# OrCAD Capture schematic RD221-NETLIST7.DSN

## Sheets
1 3: size A3
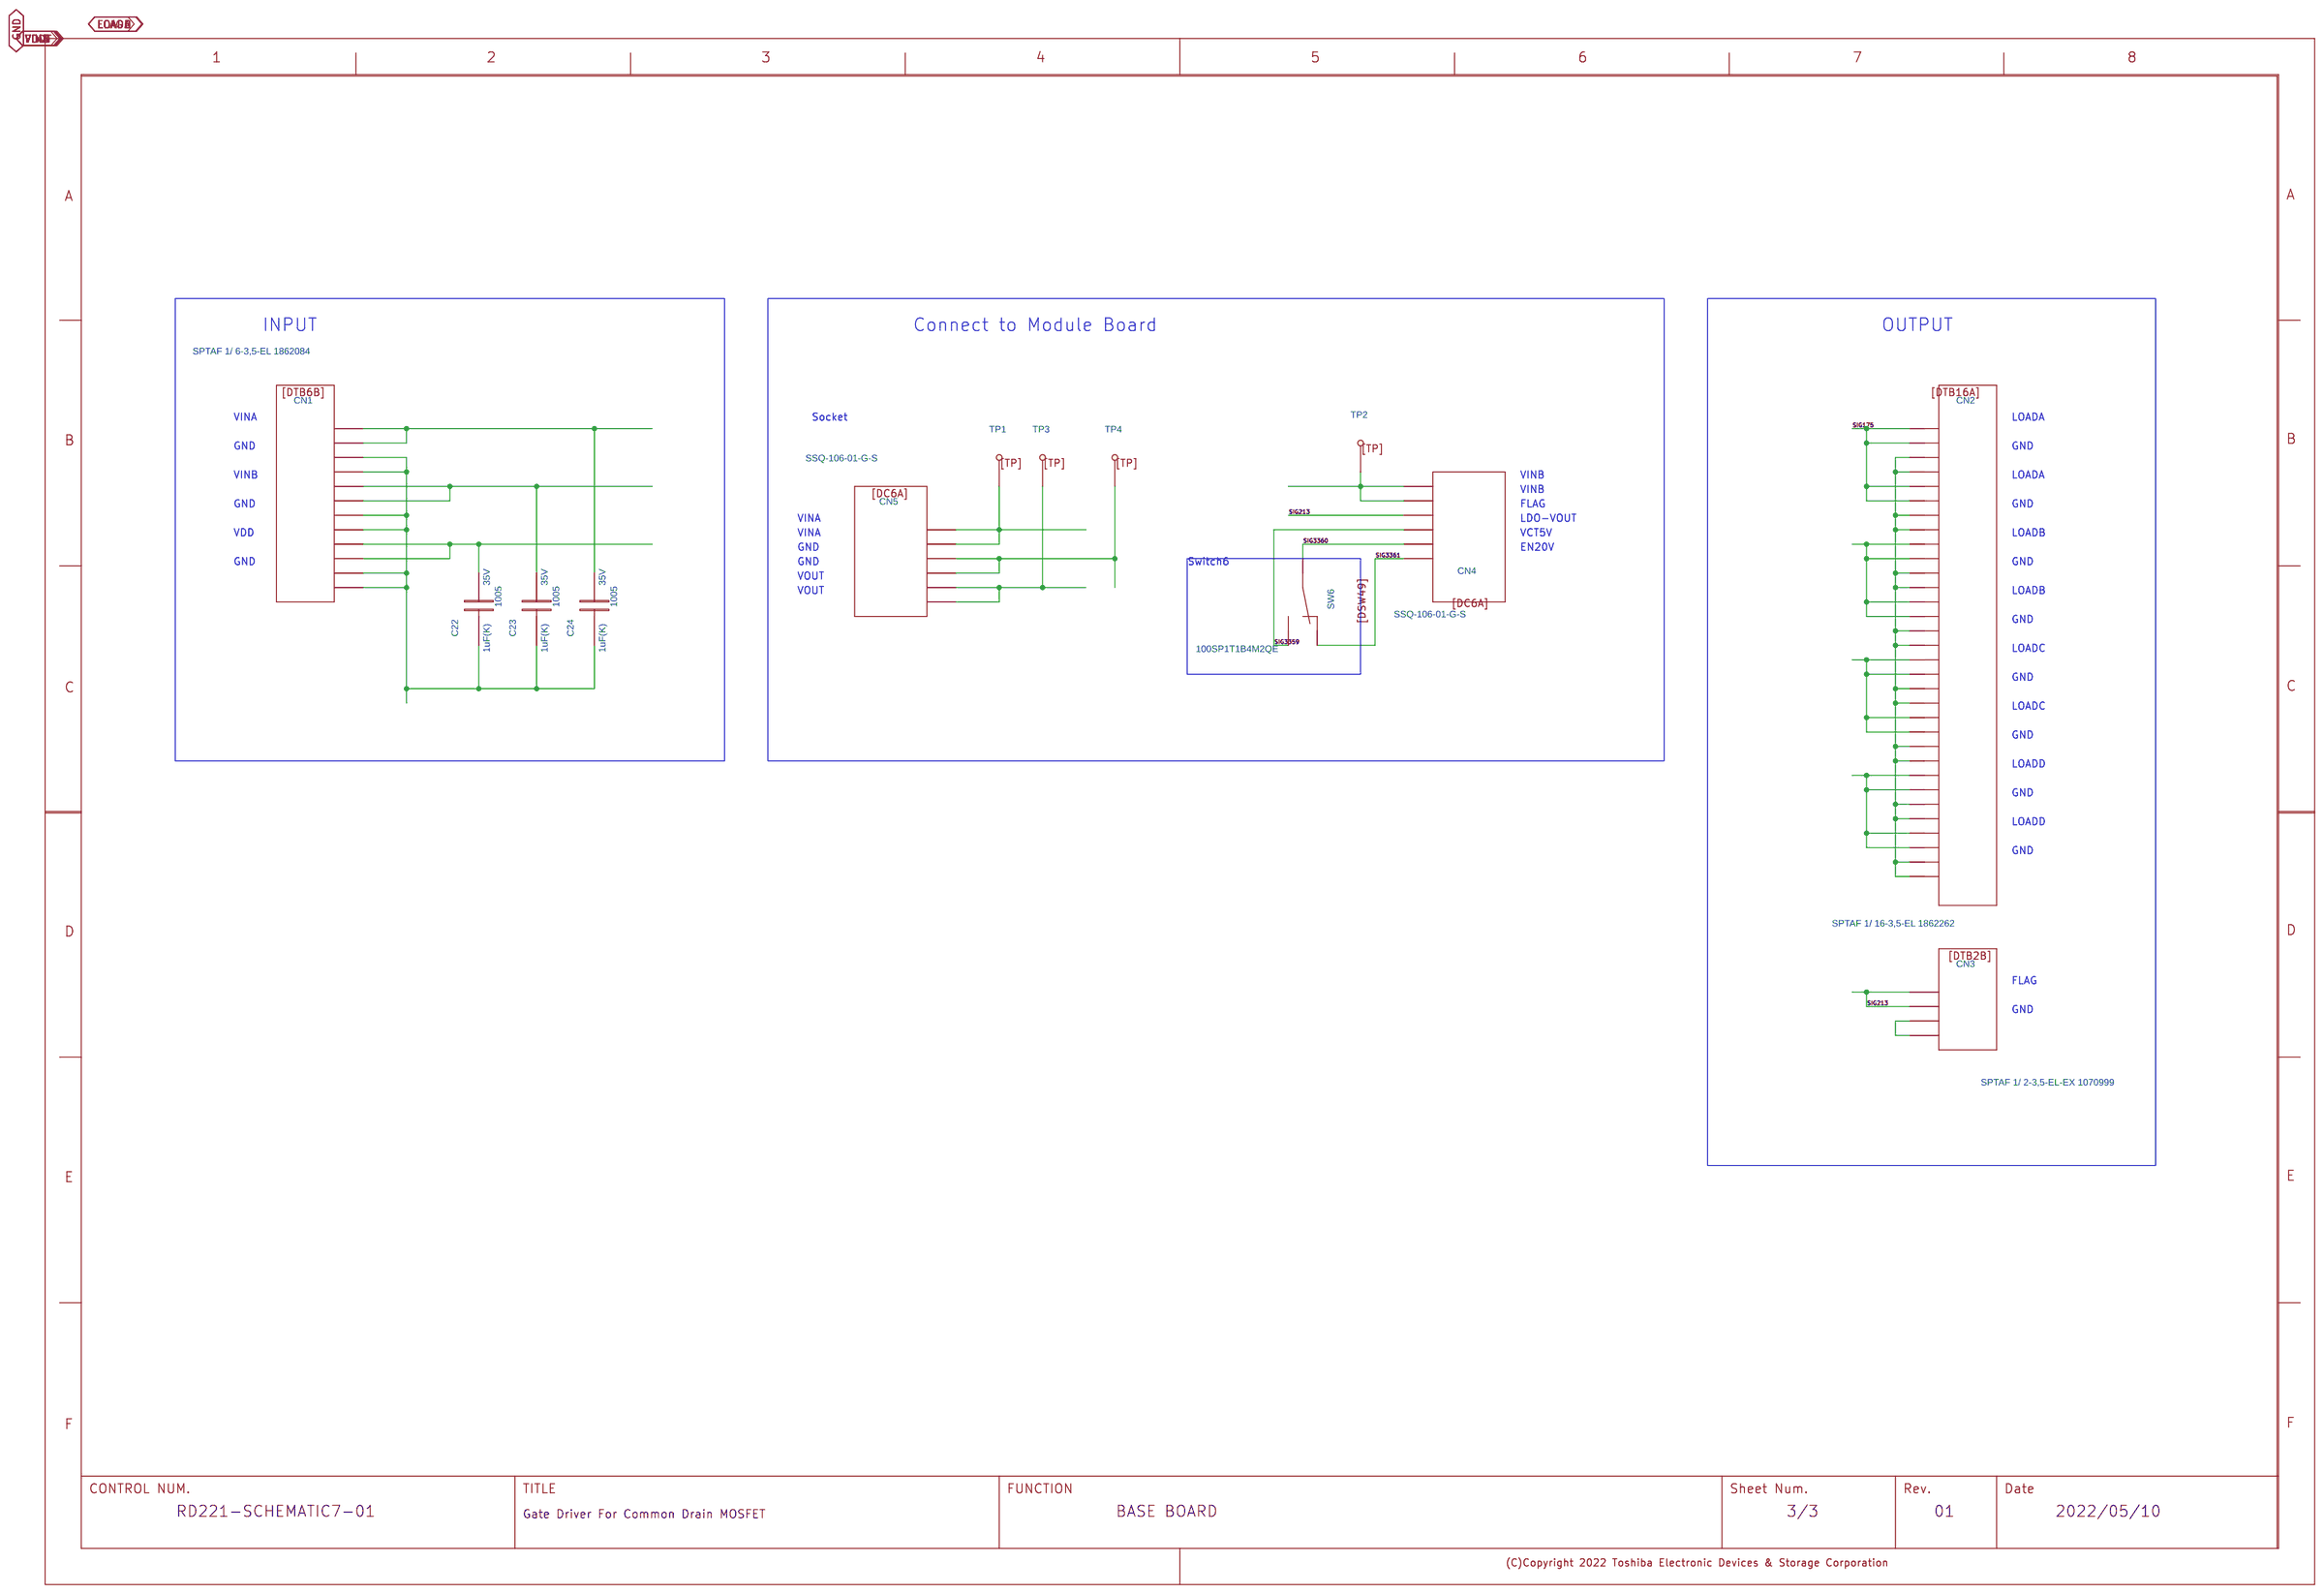
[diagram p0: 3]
2 2: size A3
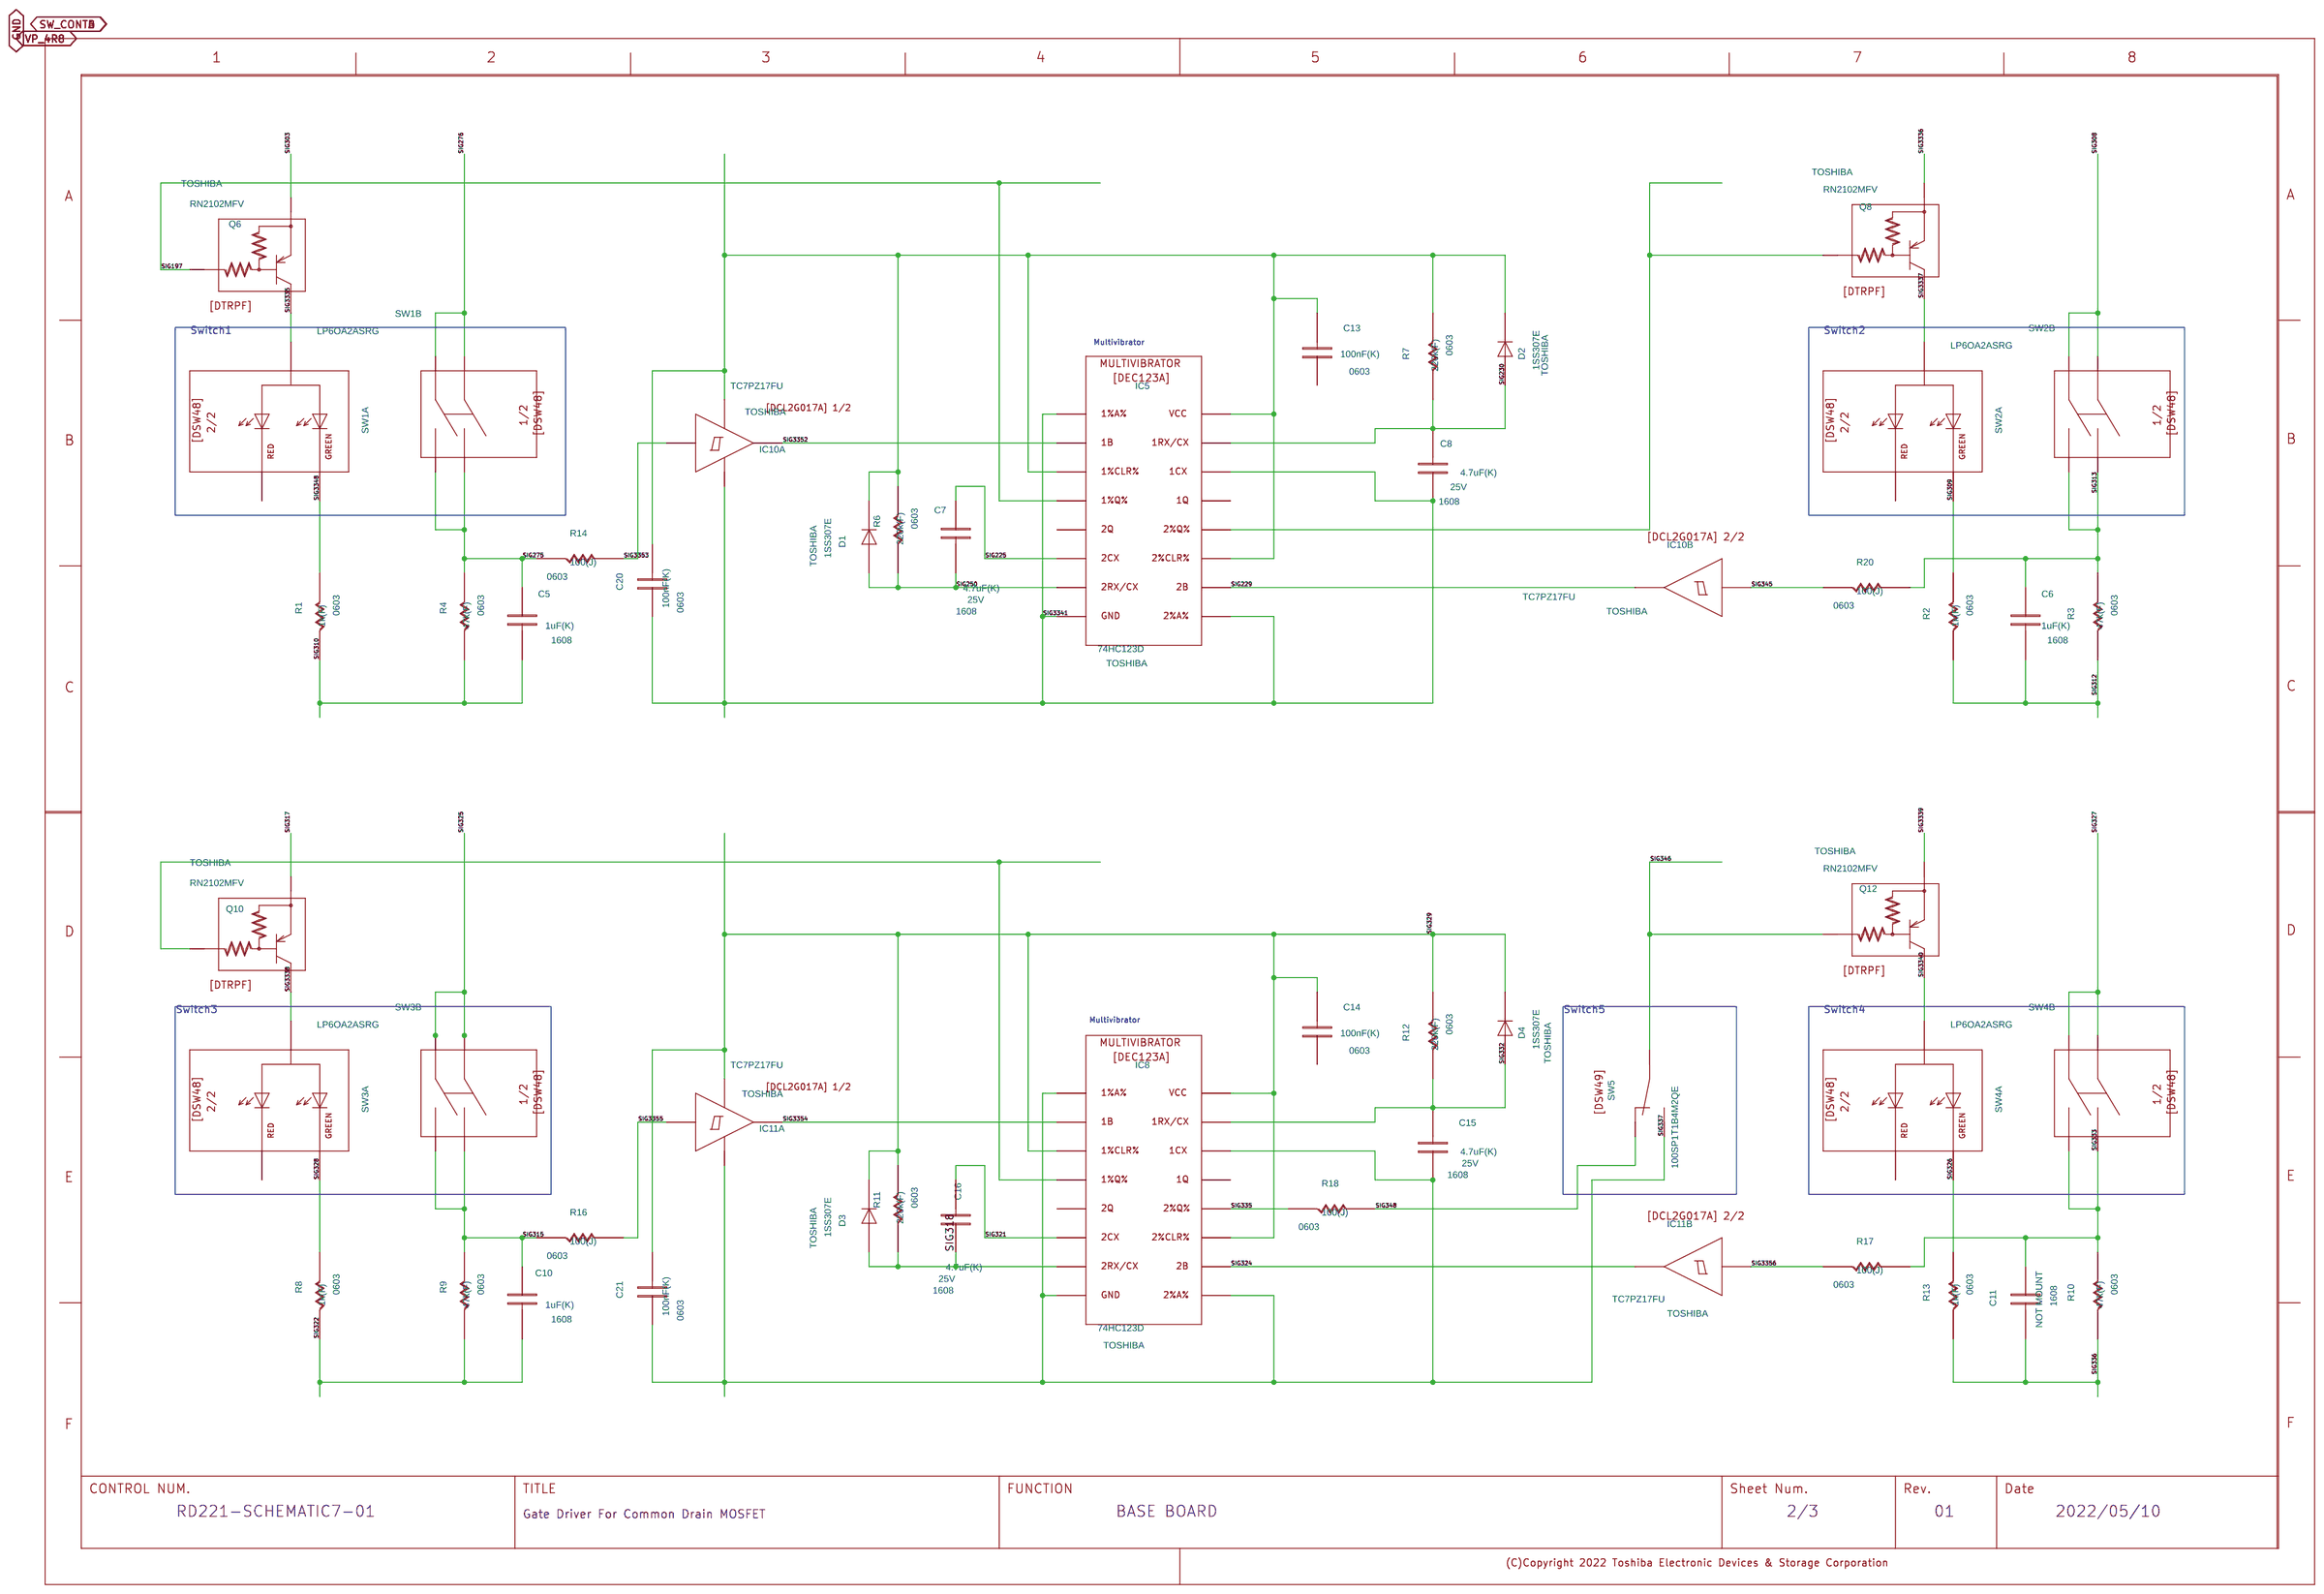
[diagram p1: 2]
3 1: size A3
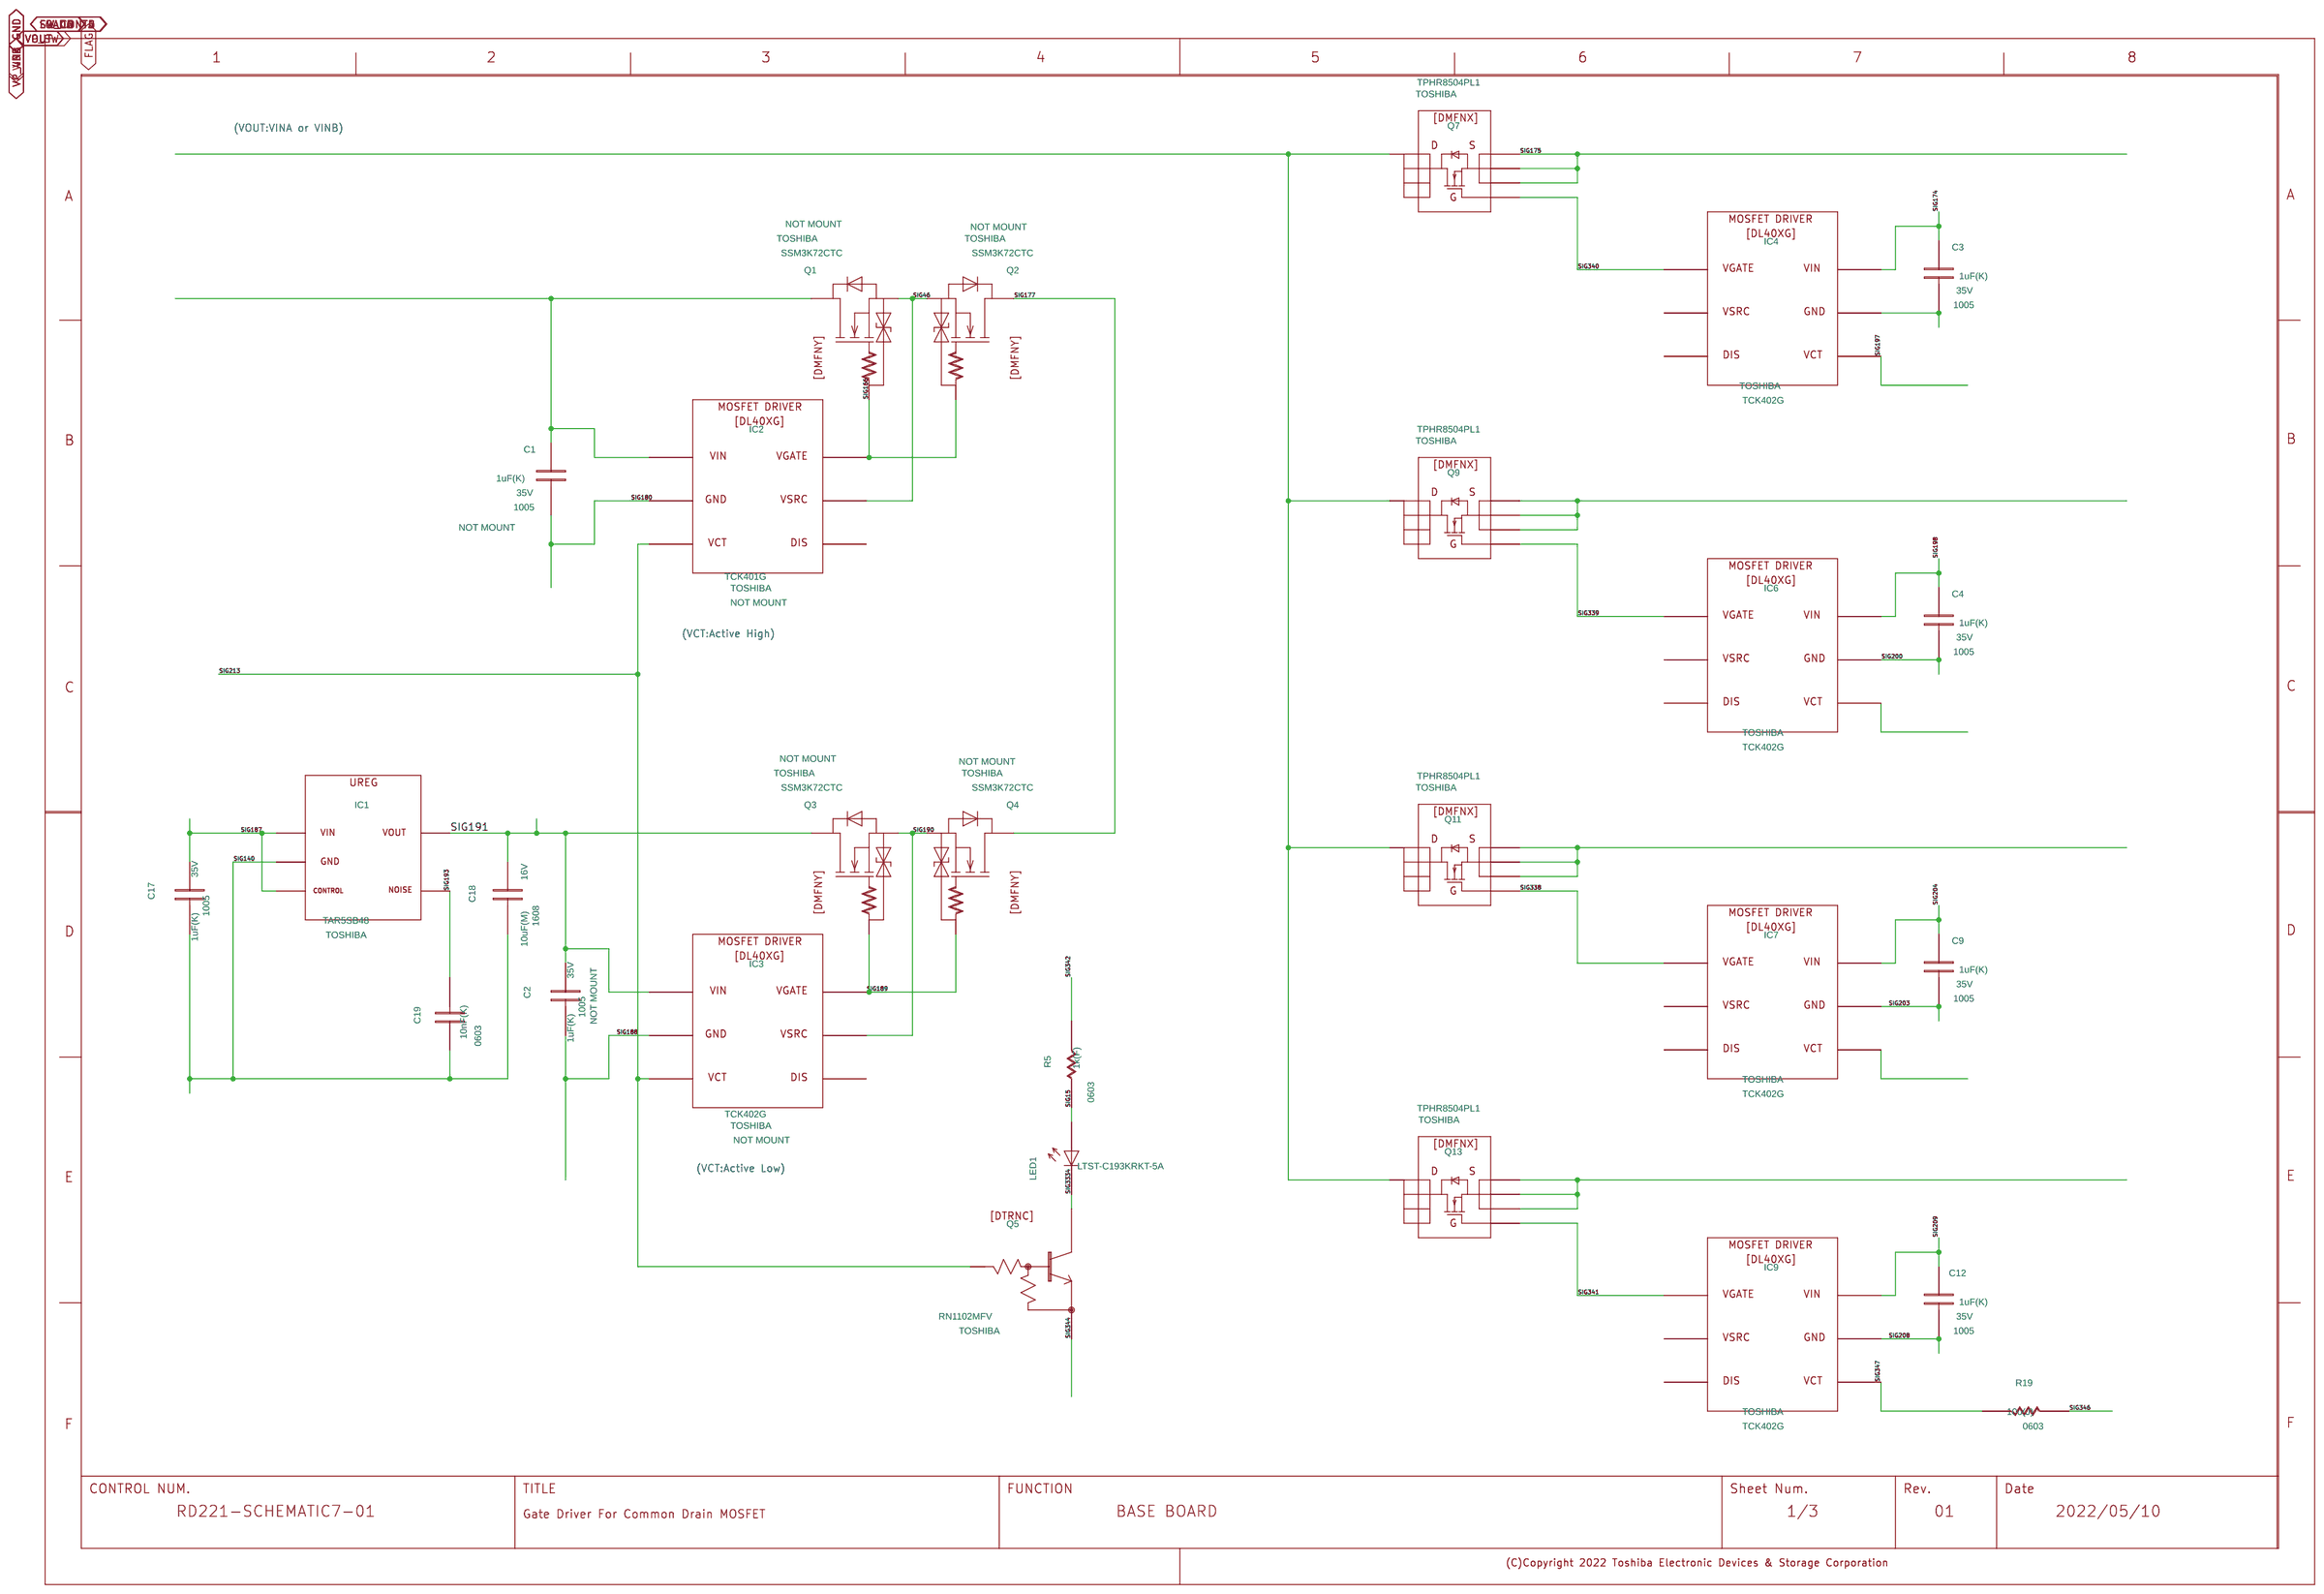
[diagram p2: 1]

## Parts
sheet 1
C1  DC
C2  DC
C3  DC
C4  DC
C9  DC
C12  DC
C17  DC
C18  DC
C19  DC
IC1  DL5SBXX
IC2  DL40XG
IC3  DL40XG
IC4  DL40XG
IC6  DL40XG
IC7  DL40XG
IC9  DL40XG
LED1  DLED
Q1  DMFNY
Q2  DMFNY
Q3  DMFNY
Q4  DMFNY
Q5  DTRNC
Q7  DMFNX
Q9  DMFNX
Q11  DMFNX
Q13  DMFNX
R5  DR
R19  DR
U?#2  WAKU_DEF100
sheet 2
C5  DC
C6  DC
C7  DC
C8  DC
C10  DC
C11  DC
C13  DC
C14  DC
C15  DC
C16  DC
C20  DC
C21  DC
D1  DD
D2  DD
D3  DD
D4  DD
IC5  DEC123A
IC8  DEC123A
IC10  DCL2G017A_1  (sections A,B)
IC11  DCL2G017A_1  (sections A,B)
Q6  DTRPF
Q8  DTRPF
Q10  DTRPF
Q12  DTRPF
R1  DR
R2  DR
R3  DR
R4  DR
R6  DR
R7  DR
R8  DR
R9  DR
R10  DR
R11  DR
R12  DR
R13  DR
R14  DR
R16  DR
R17  DR
R18  DR
R20  DR
SW1  DSW48_1  (sections A,B)
SW2  DSW48_1  (sections A,B)
SW3  DSW48_1  (sections A,B)
SW4  DSW48_1  (sections A,B)
SW5  DSW49
U?#1  WAKU_DEF100
sheet 3
C22  DC
C23  DC
C24  DC
CN1  DTB6B
CN2  DTB16A
CN3  DTB2B
CN4  DC6A
CN5  DC6A
SW6  DSW49
TP1  DTP
TP2  DTP
TP3  DTP
TP4  DTP
U?#3  WAKU_DEF100

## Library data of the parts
C1 C2 = DC: COMP: DP0000016125; COMPONENTNAME: DP0000016125_package; FUNCN: DP0000016125; GCOUNT: 1; MAXGCOUNT: 1; NOTMOUNT: NOT MOUNT; OUMEPARTTYPE: C; SIZECODESMD: 1005; VAL1: 1uF(K); VAL2: 35V; VAL3: GRM155R6YA105KE11D
C3 C4 C9 C12 C17 C22-C24 = DC: COMP: DP0000016125; COMPONENTNAME: DP0000016125_package; FUNCN: DP0000016125; GCOUNT: 1; MAXGCOUNT: 1; OUMEPARTTYPE: C; SIZECODESMD: 1005; VAL1: 1uF(K); VAL2: 35V; VAL3: GRM155R6YA105KE11D
C18 = DC: COMP: DP0008993000; COMPONENTNAME: DP0008993000_package; FUNCN: DP0008993000; GCOUNT: 1; MAXGCOUNT: 1; OUMEPARTTYPE: C; SIZECODESMD: 1608; VAL1: 10uF(M); VAL2: 16V; VAL3: GRM188R61C106MA73D
C19 = DC: COMP: DP0000015127; COMPONENTNAME: DP0000015127; FUNCN: DP0000015127; GCOUNT: 1; MAXGCOUNT: 1; OUMEPARTTYPE: C; SIZECODESMD: 0603; VAL1: 10nF(K); VAL2: 16V; VAL3: GRM033B31C103KA12D
IC1 = DL5SBXX: COMP: DP0010569000; COMPONENTNAME: DP0010569000_package; FUNCN: DP0010569000; GCOUNT: 1; MAXGCOUNT: 1; OUMEPARTTYPE: IC; SAVEAREA0: -49052,-25553,79781,45765; SAVECOUNT: 22; UPDATEDATE: 2021/11/04; UPDATETIME: 15:26:52; USERCOMPTEXT3: TOSHIBA; VAL1: TAR5SB48; VAL3: TAR5SB48
IC2 = DL40XG: COMP: DP0010565000; COMPONENTNAME: DP0010565000_package; FUNCN: DP0010565000; GCOUNT: 1; MAXGCOUNT: 1; NOTMOUNT: NOT MOUNT; OUMEPARTTYPE: IC; SAVEAREA0: -25087,-13639,60802,33906; UPDATEDATE: 2021/11/04; UPDATETIME: 14:00:32; UPDATEUSER: t5459927; USERCOMPTEXT3: TOSHIBA; VAL1: TCK401G; VAL3: TCK401G
IC3 = DL40XG: COMP: DP0010566000; COMPONENTNAME: DP0010566000_package; FUNCN: DP0010566000; GCOUNT: 1; MAXGCOUNT: 1; NOTMOUNT: NOT MOUNT; OUMEPARTTYPE: IC; SAVEAREA0: -25087,-13639,60802,33906; UPDATEDATE: 2021/11/04; UPDATETIME: 14:00:32; UPDATEUSER: t5459927; USERCOMPTEXT3: TOSHIBA; VAL1: TCK402G; VAL3: TCK402G
IC4 IC6 IC7 IC9 = DL40XG: COMP: DP0010566000; COMPONENTNAME: DP0010566000_package; FUNCN: DP0010566000; GCOUNT: 1; MAXGCOUNT: 1; OUMEPARTTYPE: IC; SAVEAREA0: -25087,-13639,60802,33906; UPDATEDATE: 2021/11/04; UPDATETIME: 14:00:32; UPDATEUSER: t5459927; USERCOMPTEXT3: TOSHIBA; VAL1: TCK402G; VAL3: TCK402G
LED1 = DLED: COMP: DP0010573000; COMPONENTNAME: DP0010573000_package; FUNCN: DP0010573000; GCOUNT: 1; MAXGCOUNT: 1; OUMEPARTTYPE: DS; VAL3: LTST-C193KRKT-5A
Q1-Q4 = DMFNY: COMP: DP0010564000; COMPONENTNAME: DP0010564000_package; FUNCN: DP0010564000; GCOUNT: 1; MAXGCOUNT: 1; NOTMOUNT: NOT MOUNT; OUMEPARTTYPE: Q; USERCOMPTEXT3: TOSHIBA; VAL1: SSM3K72CTC; VAL3: SSM3K72CTC
Q5 = DTRNC: COMP: DP0010015000; COMPONENTNAME: DP0010015000_package; FUNCN: DP0010015000; GCOUNT: 1; MAXGCOUNT: 1; OUMEPARTTYPE: Q; USERCOMPTEXT1: RN1102MFV; USERCOMPTEXT3: TOSHIBA; VAL1: RN1114MFV; VAL3: RN1114MFV
Q7 Q9 Q11 Q13 = DMFNX: COMP: DP0010567000; COMPONENTNAME: DP0010567000_package; FUNCN: DP0010567000; GCOUNT: 1; MAXGCOUNT: 1; OUMEPARTTYPE: Q; USERCOMPTEXT3: TOSHIBA; VAL1: TPHR8504PL1; VAL3: TPHR8504PL1
R1 R2 R5 R8 R13 = DR: COMP: DP0000152048; COMPONENTNAME: DP0000152048; FUNCN: DP0000152048; GCOUNT: 1; MAXGCOUNT: 1; OUMEPARTTYPE: R; SIZECODESMD: 0603; VAL1: 1k(F); VAL2: 50mW; VAL3: ERJ1GNF1001C
R14 R16-R20 = DR: COMP: DP0000155000; COMPONENTNAME: DP0000155000_package; FUNCN: DP0000155000; GCOUNT: 1; MAXGCOUNT: 1; OUMEPARTTYPE: R; SIZECODESMD: 0603; VAL1: 100(J); VAL2: 50mW; VAL3: RK73B1HTTC101J
U?#2 = WAKU_DEF100: DATE: 2022/05/10; DRAWINGNUMBER: RD221-SCHEMATIC7-01; FUNCTION: BASE BOARD; REVISION: 01; SAVEAREA0: 148187,-66180,486823,89919; SAVECOUNT: 6; SHEETNUMBER: 1/3; TITLE: Gate Driver For Common Drain MOSFET; UPDATEDATE: 2022/05/17; UPDATETIME: 07:15:59
C5 C6 C10 = DC: COMP: DP0000149011; COMPONENTNAME: DP0000149011_package; FUNCN: DP0000149011; GCOUNT: 1; MAXGCOUNT: 1; OUMEPARTTYPE: C; SIZECODESMD: 1608; VAL1: 1uF(K); VAL2: 35V; VAL3: GMK107BJ105KA-T
C7 C8 C15 C16 = DC: COMP: DP0000017116; COMPONENTNAME: DP0000017116_package; FUNCN: DP0000017116; GCOUNT: 1; MAXGCOUNT: 1; OUMEPARTTYPE: C; SIZECODESMD: 1608; VAL1: 4.7uF(K); VAL2: 25V; VAL3: GRM188R61E475KE15D
C11 = DC: COMP: DP0000149011; COMPONENTNAME: DP0000149011_package; FUNCN: DP0000149011; GCOUNT: 1; MAXGCOUNT: 1; NOTMOUNT: NOT MOUNT; OUMEPARTTYPE: C; SIZECODESMD: 1608; VAL1: 1uF(K); VAL2: 35V; VAL3: GMK107BJ105KA-T
C13 C14 C20 C21 = DC: COMP: DP0000015406; COMPONENTNAME: DP0000015406_package; FUNCN: DP0000015406; GCOUNT: 1; MAXGCOUNT: 1; OUMEPARTTYPE: C; SIZECODESMD: 0603; VAL1: 100nF(K); VAL2: 16V; VAL3: GRM033R61C104KE14D
D1-D4 = DD: COMP: DP0005002000; COMPONENTNAME: DP0005002000_package; FUNCN: DP0005002000; GCOUNT: 1; MAXGCOUNT: 1; OUMEPARTTYPE: D; USERCOMPTEXT3: TOSHIBA; VAL1: 1SS307E; VAL3: 1SS307E
IC5 IC8 = DEC123A: COMP: DP0010568000; COMPONENTNAME: DP0010568000_package; FUNCN: DP0010568000; GCOUNT: 1; MAXGCOUNT: 1; OUMEPARTTYPE: IC; USERCOMPTEXT3: TOSHIBA; VAL1: 74HC123D; VAL3: 74HC123D
IC10 IC11 = DCL2G017A_1: COMP: DP0010608000; COMPONENTNAME: DCL2G017A_pinAssign_DCL2G017A_1_function; CaptureCellPackProp: DCL2G017A_1A; FUNCN: DCL2G017A_1_function; GCOUNT: 1; MAXGCOUNT: 1; OUMEPARTTYPE: IC; USERCOMPTEXT3: TOSHIBA; VAL1: TC7PZ17FU; VAL3: TC7PZ17FU
Q6 Q8 Q10 Q12 = DTRPF: COMP: DP0010570000; COMPONENTNAME: DP0010570000_package; FUNCN: DP0010570000; GCOUNT: 1; MAXGCOUNT: 1; OUMEPARTTYPE: Q; USERCOMPTEXT3: TOSHIBA; VAL1: RN2102MFV; VAL3: RN2102MFV
R3 R4 R9 R10 = DR: COMP: DP0000152088; COMPONENTNAME: DP0000152088; FUNCN: DP0000152088; GCOUNT: 1; MAXGCOUNT: 1; OUMEPARTTYPE: R; SIZECODESMD: 0603; VAL1: 47k(F); VAL2: 50mW; VAL3: ERJ1GNF4702C
R6 R11 = DR: COMP: DP0000152104; COMPONENTNAME: DP0000152104; FUNCN: DP0000152104; GCOUNT: 1; MAXGCOUNT: 1; OUMEPARTTYPE: R; SIZECODESMD: 0603; VAL1: 220k(F); VAL2: 50mW; VAL3: ERJ1GNF2203C
R7 R12 = DR: COMP: DP0000155128; COMPONENTNAME: DP0000155128; FUNCN: DP0000155128; GCOUNT: 1; MAXGCOUNT: 1; OUMEPARTTYPE: R; SIZECODESMD: 0603; VAL1: 220k(F); VAL2: 50mW; VAL3: RK73B1HTTC224J
SW1 SW4 = DSW48_1: COMP: DP0010571000; COMPONENTNAME: DSW48_pinAssign_DSW48_1_function; CaptureCellPackProp: DSW48_1B; FUNCN: DSW48_1_function; GCOUNT: 1; MAXGCOUNT: 1; OUMEPARTTYPE: S; VAL3: LP6OA2ASRG; ADSCNVFLAG: ON; FNLEADFREETHET1GT2GMCTH1: N_N_N; MOUNTINGFORM: ‘}“üŽÀ‘•; NUMBEROFPOSITIO: 2POS; OUMECLASSIFICATION: vbV{^^^NgXCb`; OUMEMAKER: ZZZ bè; OUMEMAKERKATAMEI: LP6OA2ASRG; RATEDCURRENT: 12m; RATEDVOLTAGE: 12
SW2 = DSW48_1: COMP: DP0010571000; COMPONENTNAME: DSW48_pinAssign_DSW48_2_function; CaptureCellPackProp: DSW48_1A; FUNCN: DSW48_2_function; GCOUNT: 1; MAXGCOUNT: 1; OUMEPARTTYPE: S; VAL3: LP6OA2ASRG; ADSCNVFLAG: ON; FNLEADFREETHET1GT2GMCTH1: N_N_N; MOUNTINGFORM: ‘}“üŽÀ‘•; NUMBEROFPOSITIO: 2POS; OUMECLASSIFICATION: vbV{^^^NgXCb`; OUMEMAKER: ZZZ bè; OUMEMAKERKATAMEI: LP6OA2ASRG; RATEDCURRENT: 12m; RATEDVOLTAGE: 12
SW3 = DSW48_1: ADSCNVFLAG: ON; COMP: DP0010571000; COMPONENTNAME: DSW48_pinAssign_DSW48_2_function; CaptureCellPackProp: DSW48_1A; FNLEADFREETHET1GT2GMCTH1: N_N_N; FUNCN: DSW48_2_function; GCOUNT: 1; MAXGCOUNT: 1; MOUNTINGFORM: ‘}“üŽÀ‘•; NUMBEROFPOSITIO: 2POS; OUMECLASSIFICATION: vbV{^^^NgXCb`; OUMEMAKER: ZZZ bè; OUMEMAKERKATAMEI: LP6OA2ASRG; OUMEPARTTYPE: S; RATEDCURRENT: 12m; RATEDVOLTAGE: 12; VAL3: LP6OA2ASRG
SW5 SW6 = DSW49: COMP: DP0010575000; COMPONENTNAME: DP0010575000_package; FUNCN: DP0010575000; GCOUNT: 1; MAXGCOUNT: 1; OUMEPARTTYPE: S; VAL3: 100SP1T1B4M2QE
U?#1 = WAKU_DEF100: DATE: 2022/05/10; DRAWINGNUMBER: RD221-SCHEMATIC7-01; FUNCTION: BASE BOARD; REVISION: 01; SAVEAREA0: 148187,-66180,486823,89919; SAVECOUNT: 6; SHEETNUMBER: 2/3; TITLE: Gate Driver For Common Drain MOSFET; UPDATEDATE: 2022/05/16; UPDATETIME: 16:52:10
CN1 = DTB6B: COMP: DP0010576000; COMPONENTNAME: DP0010576000_package; FUNCN: DP0010576000; GCOUNT: 1; MAXGCOUNT: 1; OUMEPARTTYPE: TB; VAL3: SPTAF 1/ 6-3,5-EL 1862084
CN2 = DTB16A: COMP: DP0010577000; COMPONENTNAME: DP0010577000_package; FUNCN: DP0010577000; GCOUNT: 1; MAXGCOUNT: 1; OUMEPARTTYPE: TB; VAL3: SPTAF 1/ 16-3,5-EL 1862262
CN3 = DTB2B: COMP: DP0010578000; COMPONENTNAME: DP0010578000_package; FUNCN: DP0010578000; GCOUNT: 1; MAXGCOUNT: 1; OUMEPARTTYPE: TB; VAL3: SPTAF 1/ 2-3,5-EL-EX 1070999
CN4 CN5 = DC6A: COMP: DP0010574000; COMPONENTNAME: DP0010574000_package; FUNCN: DP0010574000; GCOUNT: 1; MAXGCOUNT: 1; OUMEPARTTYPE: CN; VAL3: SSQ-106-01-G-S
TP1-TP4 = DTP: COMP: DP9000817000; COMPONENTNAME: DP9000817000_package; FUNCN: DP9000817000; GCOUNT: 1; MAXGCOUNT: 1; NOTMOUNT: NOT MOUNT; OUMEPARTTYPE: TP
U?#3 = WAKU_DEF100: DATE: 2022/05/10; DRAWINGNUMBER: RD221-SCHEMATIC7-01; FUNCTION: BASE BOARD; REVISION: 01; SAVEAREA0: 148187,-66180,486823,89919; SAVECOUNT: 6; SHEETNUMBER: 3/3; TITLE: Gate Driver For Common Drain MOSFET; UPDATEDATE: 2022/05/10; UPDATETIME: 18:03:24

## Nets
GND: C1.2 C2.2 C3.2 C4.2 C5.2 C6.2 C8.1 C9.2 C10.2 C11.2 C12.2 C13.1 C14.1 C15.1 C17.2 C18.2 C19.1 C20.1 C21.1 C22.2 C23.2 C24.2 CN1.2 CN1.2A CN1.4 CN1.4A CN1.6 CN1.6A CN2.2 CN2.2A CN2.4 CN2.4A CN2.6 CN2.6A CN2.8 CN2.8A CN2.10 CN2.10A CN2.12 CN2.12A CN2.14 CN2.14A CN2.16 CN2.16A CN3.2 CN3.2A CN5.3 CN5.4 IC1.2 IC2.B2 IC3.B2 IC4.B2 IC5.1 IC5.8 IC5.9 IC5.14 IC6.B2 IC7.B2 IC8.1 IC8.8 IC8.9 IC8.14 IC9.B2 IC10.2 IC11.2 Q5.E R1.2 R2.2 R3.2 R4.2 R8.2 R9.2 R10.2 R13.2 SW5.3 TP4.1
VDD: C17.1 C22.1 CN1.5 CN1.5A IC1.1 IC1.3
VINA: C1.1 C24.1 CN1.1 CN1.1A CN5.1 CN5.2 IC2.A2 Q1.D TP1.1
VINB: C23.1 CN1.3 CN1.3A CN4.5 CN4.6 TP2.1
FLAG: CN3.1 CN3.1A CN4.4 IC2.C2 IC3.C2 Q5.B
LOADA: CN2.1 CN2.1A CN2.3 CN2.3A Q7.1 Q7.2 Q7.3
LOADB: CN2.5 CN2.5A CN2.7 CN2.7A Q9.1 Q9.2 Q9.3
LOADC: CN2.9 CN2.9A CN2.11 CN2.11A Q11.1 Q11.2 Q11.3
LOADD: CN2.13 CN2.13A CN2.15 CN2.15A Q13.1 Q13.2 Q13.3
SIG15: LED1.A R5.1
SIG46: IC2.B1 Q1.S Q2.S
SIG166: IC2.A1 Q1.G Q2.G
SIG189: IC3.A1 Q3.G Q4.G
SIG190: IC3.B1 Q3.S Q4.S
SIG193: C19.2 IC1.4
SIG225: C7.1 IC5.6
SIG229: IC5.10 IC10.4
SIG230: C8.2 D2.A IC5.15 R7.2
SIG250: C7.2 D1.A IC5.7 R6.2
SIG275: C5.1 R4.1 R14.2 SW1.2 SW1.4
SIG309: R2.1 SW2.L2
SIG313: C6.1 R3.1 R20.1 SW2.2 SW2.4
SIG315: C10.1 R9.1 R16.2 SW3.2 SW3.4
SIG318: C16.1 D3.A IC8.7 R11.2
SIG321: C16.2 IC8.6
SIG324: IC8.10 IC11.4
SIG326: R13.1 SW4.L2
SIG328: R8.1 SW3.L2
SIG332: C15.2 D4.A IC8.15 R12.2
SIG333: C11.1 R10.1 R17.1 SW4.2 SW4.4
SIG335: IC8.12 R18.2
SIG338: IC7.A1 Q11.4
SIG339: IC6.A1 Q9.4
SIG340: IC4.A1 Q7.4
SIG341: IC9.A1 Q13.4
SIG345: IC10.3 R20.2
SIG347: IC9.C2 R19.2
SIG348: R18.1 SW5.1
SIG3334: LED1.C Q5.C
SIG3335: Q6.C SW1.LC
SIG3337: Q8.C SW2.LC
SIG3338: Q10.C SW3.LC
SIG3340: Q12.C SW4.LC
SIG3348: R1.1 SW1.L2
SIG3352: IC5.2 IC10.6
SIG3353: IC10.1 R14.1
SIG3354: IC8.2 IC11.6
SIG3355: IC11.1 R16.1
SIG3356: IC11.3 R17.2
SIG3359: CN4.3 SW6.3
SIG3360: CN4.2 SW6.2
SIG3361: CN4.1 SW6.1
SW_CONTA: IC4.C2 IC5.4 Q6.B
SW_CONTB: IC5.12 IC6.C2 Q8.B
SW_CONTC: IC7.C2 IC8.4 Q10.B
SW_CONTD: Q12.B R19.1 SW5.2
VOUT: C3.1 C4.1 C9.1 C12.1 CN5.5 CN5.6 IC4.A2 IC6.A2 IC7.A2 IC9.A2 Q7.5 Q9.5 Q11.5 Q13.5 TP3.1
VP_4R8: C2.1 C13.2 C14.2 C18.1 C20.2 C21.2 D1.C D2.C D3.C D4.C IC1.5 IC3.A2 IC5.3 IC5.11 IC5.16 IC8.3 IC8.11 IC8.16 IC10.5 IC11.5 Q3.D Q6.E Q8.E Q10.E Q12.E R5.2 R6.1 R7.1 R11.1 R12.1 SW1.1 SW1.3 SW2.1 SW2.3 SW3.1 SW3.3 SW4.1 SW4.3
VP_SW: Q2.D Q4.D

Not connected (* = marked no-connect by the designer): IC2 C1; IC3 C1; IC4 B1 C1; IC5 5 13; IC6 B1 C1; IC7 B1 C1; IC8 5 13; IC9 B1 C1; SW1 L1; SW2 L1; SW3 L1; SW4 L1

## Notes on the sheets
sheet 1
- INPUT
- Connect to Module Board
- OUTPUT
- VINA
- Socket
- LOADA
- GND
- GND
- VINB
- VINB
- LOADA
- VINB
- GND
- VINA
- FLAG
- LDO-VOUT
- GND
- VDD
- VINA
- VCT5V
- LOADB
- GND
- EN20V
- GND
- GND
- Switch6
- GND
- VOUT
- VOUT
- LOADB
- GND
- LOADC
- GND
- LOADC
- GND
- LOADD
- GND
- LOADD
- GND
- FLAG
- GND
sheet 2
- Switch1
- Switch2
- Multivibrator
- Switch3
- Switch5
- Switch4
- Multivibrator
sheet 3
- (VOUT:VINA or VINB)
- (VCT:Active High)
- (VCT:Active Low)
